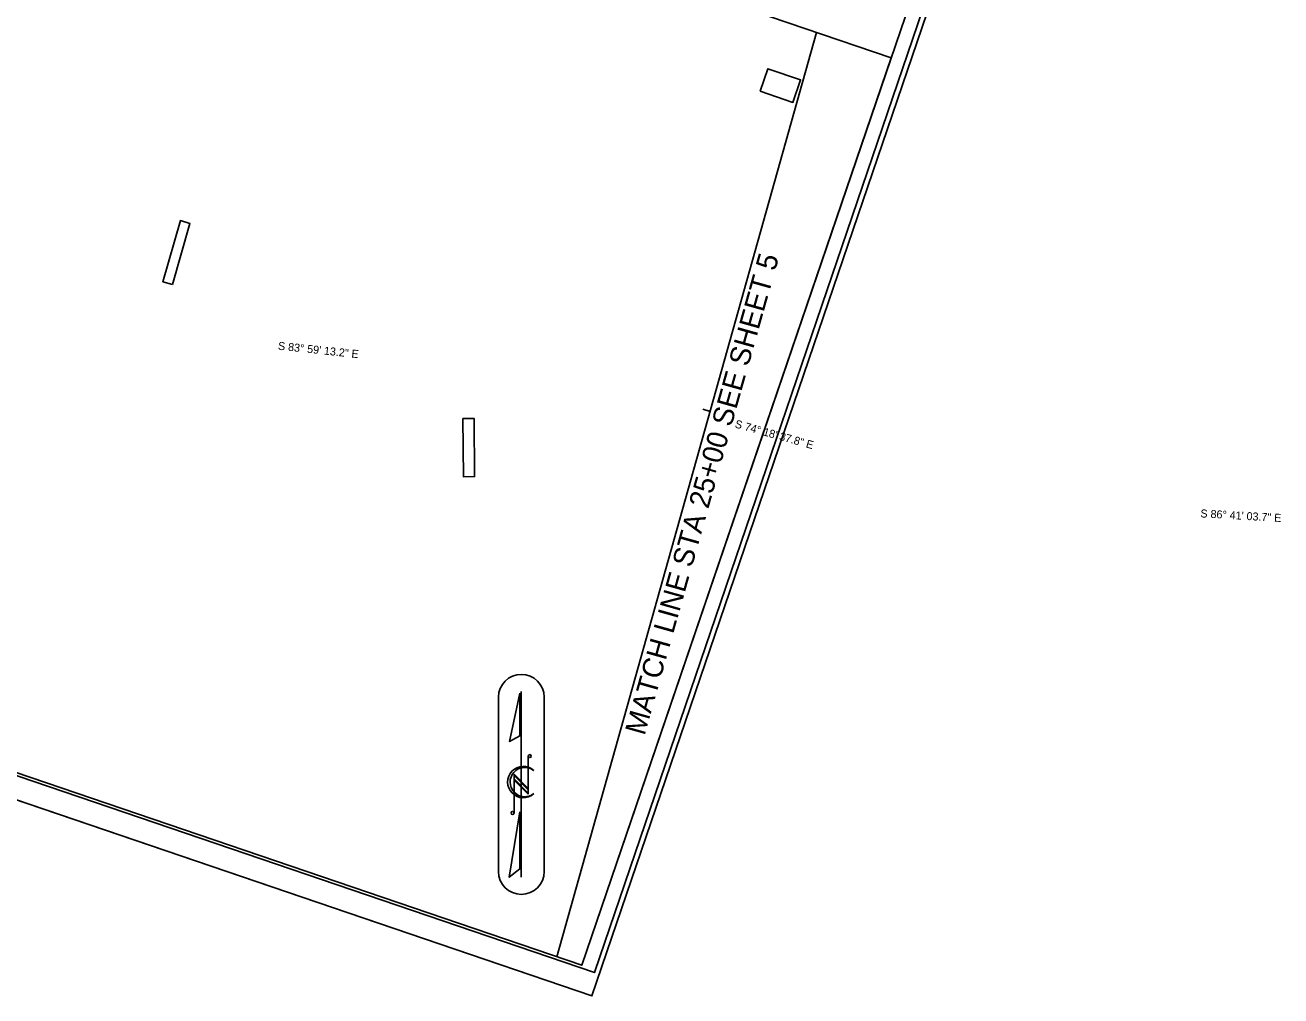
# Model space of a CAD drawing. Extents: x 927646 to 937215, y 684320 to 686920.
# Drawn here: x 928744 to 929842, y 685341 to 686190 of the extents above; entities that cross this region are included whole.
import ezdxf

# ---------------------------------------------------------------- set-up
doc = ezdxf.new("R2010")
doc.units = 0
for name, color, linetype in [('Default', 7, 'Continuous'), ('Exist Horizontal Alignment Direction Label', 7, 'Continuous'), ('Exist Horizontal Alignment Station Label', 7, 'Continuous'), ('Matchline', 7, 'Continuous'), ('Matchline Text', 7, 'Continuous'), ('Prop DSN Text', 7, 'Continuous'), ('Sheet Cutting Line CELL', 7, 'Continuous'), ('Sheet Plan CELL', 7, 'Continuous'), ('Sheet Plan Layout CELL', 7, 'Continuous'), ('Sheet Plot Border Inside CELL', 7, 'Continuous'), ('Sheet Plot Border Outside CELL', 7, 'Continuous')]:
    doc.layers.add(name, color=color, linetype=linetype)

msp = doc.modelspace()

# ---------------------------------------------------------------- linework, layer by layer
at = {"layer": 'Default'}
msp.add_line((929342.7, 685851.9), (929336.4, 685854.1), dxfattribs=at)
at = {"layer": 'Exist Horizontal Alignment Station Label'}
for p, q in [((929157.6, 685602.1), (929157.6, 685449.6)), ((929157.6, 685449.6), (929157.6, 685602.1)), ((929197.6, 685602.1), (929197.6, 685449.6)), ((929197.6, 685602.1), (929197.6, 685449.6))]:
    msp.add_line(p, q, dxfattribs=at)
for points in [[(928872.6, 685963.1), (928887.9, 686016.6), (928879.5, 686019), (928864.2, 685965.5)], [(929126.6, 685845.8), (929126.9, 685795), (929136.7, 685795.1), (929136.4, 685845.8)]]:
    msp.add_lwpolyline(points, close=True, dxfattribs=at)
for centre, start, end in [((929177.6, 685602.1), 90, 180), ((929177.6, 685602.1), 90, 180), ((929177.6, 685602.1), 0, 90), ((929177.6, 685602.1), 0, 90), ((929177.6, 685449.6), 180, 270), ((929177.6, 685449.6), 180, 270), ((929177.6, 685449.6), 270, 0), ((929177.6, 685449.6), 270, 0)]:
    msp.add_arc(centre, 20, start, end, dxfattribs=at)
at = {"layer": 'Matchline'}
msp.add_line((929435.8, 686183.6), (929208.7, 685375.1), dxfattribs=at)
at = {"layer": 'Prop DSN Text'}
msp.add_lwpolyline([(929386.4, 686132.1), (929415, 686122.4), (929421.7, 686142), (929393.1, 686151.8)], close=True, dxfattribs=at)
at = {"layer": 'Sheet Cutting Line CELL'}
msp.add_line((927645.8, 685883.9), (929239.3, 685340.9), dxfattribs=at)
at = {"layer": 'Sheet Plan CELL'}
for p, q in [((929177.6, 685444.6), (929177.6, 685607.1)), ((929183.7, 685550.6), (929183.7, 685517.2)), ((929188.3, 685538.2), (929188.5, 685538)), ((929183.7, 685522.4), (929171.3, 685534.9)), ((929171.3, 685534.9), (929171.3, 685501)), ((929183.7, 685521.2), (929171.3, 685533.6)), ((929171.3, 685533.6), (929171.3, 685530.6)), ((929183.7, 685518.2), (929171.3, 685530.6)), ((929171.3, 685530.6), (929183.7, 685518.2)), ((929183.7, 685517.2), (929171.3, 685529.7)), ((929183.7, 685518.2), (929183.7, 685521.2))]:
    msp.add_line(p, q, dxfattribs=at)
for points in [[(929569.2, 686361.5), (928149.3, 686845.4), (927810.6, 685851.5), (929230.5, 685367.7)], [(929176.4, 685605.7), (929167.2, 685563.5), (929176.4, 685568.2)], [(929176.2, 685501.9), (929167, 685444.6), (929176.2, 685451.9)]]:
    msp.add_lwpolyline(points, close=True, dxfattribs=at)
for centre in [(929185, 685550.6), (929169.9, 685500.9)]:
    msp.add_circle(centre, 1.32, dxfattribs=at)
for centre, radius, start, end in [((929179.3, 685527.9), 13.7, 47.84, 312.3941), ((929180.6, 685527.9), 12.8, 53.095, 308.6287)]:
    msp.add_arc(centre, radius, start, end, dxfattribs=at)
at = {"layer": 'Sheet Plan Layout CELL'}
msp.add_lwpolyline([(928149.3, 686845.3), (927810.6, 685851.5), (929230.5, 685367.7), (929500.9, 686161.4), (929274.5, 686238.5), (929342.7, 686438.7)], close=True, dxfattribs=at)
at = {"layer": 'Sheet Plot Border Inside CELL'}
msp.add_lwpolyline([(927664.5, 685898.6), (929241.5, 685361.3), (929581.8, 686359.9), (928004.8, 686897.2)], close=True, dxfattribs=at)
at = {"layer": 'Sheet Plot Border Outside CELL'}
msp.add_lwpolyline([(927645.8, 685883.9), (929239.3, 685340.9), (929592.5, 686377.4), (927999, 686920.3)], close=True, dxfattribs=at)

# ---------------------------------------------------------------- texts
at = {"layer": 'Exist Horizontal Alignment Direction Label'}
for s, rotation, p in [('S 83%%d 59\' 13.2" E', 353.987, (928964.6, 685906.1)), ('S 74%%d 18\' 37.8" E', 344.3105, (929363.8, 685838.2)), ('S 86%%d 41\' 03.7" E', 356.6844, (929771.2, 685759.5))]:
    msp.add_text(s, height=7, rotation=rotation, dxfattribs=at).set_placement(p)
at = {"layer": 'Matchline Text'}
msp.add_text('MATCH LINE STA 25+00 SEE SHEET 5 ', height=18, rotation=74.3039, dxfattribs=at).set_placement((929285.3, 685568))

doc.saveas('drawing.dxf')
